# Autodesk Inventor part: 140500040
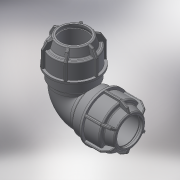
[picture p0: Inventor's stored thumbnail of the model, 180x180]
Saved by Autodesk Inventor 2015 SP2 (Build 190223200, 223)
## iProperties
Created: 2017-08
Part Number: 140500040
Material: Generic
Description: PLASSON L.14 90° ELBOW (SILVER) 40-40
Document SubType Name: Modeling
Designer: KIM
Density: 1 g/cm^3
Appearance: Default
Author: KIM
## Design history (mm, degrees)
derived "140500.ipt"
feature "Solid1::140500.ipt"
tag "TaggingFeature1"
body "Solid1"
other parameters: "d2" = 62, "d4" = 15 deg, "d5" = 40.92, "d6" = 13.5036, "d10" = 73, "d16" = 40.8, "d17" = 3.1, "d22" = 64, "d24" = 3.1, "d25" = 65.7, "d26" = 54.75, "d27" = 3.1, "d28" = 135 deg, "d29" = 1.86, "d31" = 2, "d46" = 150 deg, "d49" = 3.65, "d50" = 0, "d58" = 1.2, "d61" = 360 deg, "d63" = 36, "d80" = 57.6, "d81" = 3.2, "d84" = 3.1, "d112" = 86, "d113" = 0.86, "d115" = 90 deg, "E_" = 73, "A_" = 86, "l_" = 62
